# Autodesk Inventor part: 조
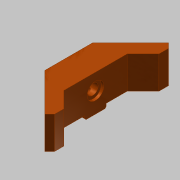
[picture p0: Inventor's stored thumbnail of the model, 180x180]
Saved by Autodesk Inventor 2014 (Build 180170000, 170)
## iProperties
Created: 2019-04
Part Number: 조
Material: 알루미늄 6061
Document SubType Name: Modeling
Designer: mduedu
Density: 1 g/cm^3
Appearance: Smooth - Light Orange
Author: mduedu
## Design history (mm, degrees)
sketch "스케치1"
  geometry: L1 (45.962, 0)-(0, -45.962); L2 (0, -45.962)-(-45.962, 0); L3 (-45.962, 0)-(0, 45.962); L4 (0, 45.962)-(45.962, 0); L5 (45.962, 0)-(-45.962, 0); L6 (0, -45.962)-(0, 45.962); 1 further point
  constraints: 12 end point, 2 midpoint, 2 parallel, 2 perpendicular, 1 horizontal
  dimensions: "d0" = 65 distance of L1.end L2.end
extrude "돌출1" new body sketch "스케치1" distance "d2" = 27; taper "d3" = 0 deg
chamfer "모따기1" distance "d4" = 25; stored, may be unused: second distance "d5" = 2, angle "d6" = 45 deg
sketch "스케치2"
  geometry: L1 (-17.678, 28.284)-(-45.962, 0) reference; L2 (-17.678, 28.284)-(17.678, 28.284) reference; L3 (45.962, 0)-(17.678, 28.284) reference; L4 (-45.962, 0)-(0, -45.962) reference; L5 (0, -45.962)-(45.962, 0) reference; L6 (-23.536, 8.284)-(23.536, 8.284); L7 (-23.536, 8.284)-(-38.891, -7.071); L8 (38.891, -7.071)-(23.536, 8.284); 1 further point
  constraints: 6 end point, 3 parallel, 2 point on line
  dimensions: "d7" = 20 distance between parallel lines of L6 L2; "d8" = 10 distance between parallel lines of L1 L7; "d9" = 10 distance between parallel lines of L3 L8
extrude "돌출2" cut sketch "스케치2" stored distance "d10" = 27; taper "d11" = 0 deg
sketch "스케치3"
  geometry: L1 (63.64, -27)-(63.64, 0) reference; L2 (56.569, -27)-(63.64, -27) reference; L3 (-28.284, -27)-(-28.284, 0) reference; L4 (-28.284, -27)-(-21.213, -27) reference; L5 (63.64, -27)-(25.678, -27); L6 (25.678, -27)-(25.678, -24); L7 (25.678, -24)-(63.64, -24); L8 (63.64, -24)-(63.64, -27); L9 (-28.284, -27)-(9.678, -27); L10 (9.678, -27)-(9.678, -24); L11 (9.678, -24)-(-28.284, -24); L12 (-28.284, -24)-(-28.284, -27); L13 (41.213, 0)-(-5.858, 0) reference; L14 (17.678, -27)-(17.678, 0)
  constraints: 18 end point, 4 parallel, 2 horizontal, 2 perpendicular, 1 midpoint, 1 symmetric about line
  dimensions: "d12" = 3 distance between parallel lines of L5 L7; "d14" = 16 distance between parallel lines of L10 L6
extrude "돌출3" cut sketch "스케치3" stored distance "d15" = 27; taper "d16" = 0 deg
sketch "스케치4"
  geometry: L1 (31.536, -27)-(15.536, -27) reference; L2 (31.536, -24)-(47.071, -24) reference; 3 further points
  constraints: 1 midpoint, 1 vertical alignment
  dimensions: "d17" = 12 distance from line of L2 point (23.536, -12)
hole "구멍1" sketch "스케치4" at (23.536, -12) diameter "d18" = 8; stored, may be unused: countersink angle "d22" = 90 deg, drill point angle "d24" = 118 deg; dims "d19" = 6, "d20" = 12.5, "d21" = 2, "d23" = 14
node "작업 평면1"
sketch "스케치5"
  geometry: L1 (0, -15)-(0, 0); L2 (-50, -4)-(50, -4); L3 (50, -4)-(50, -1.75); L4 (-50, -1.75)-(-50, -4); L5 (12, -1.75)-(12, -2.75); L6 (12, -2.75)-(-12, -2.75); L7 (-12, -2.75)-(-12, -1.75); L8 (50, -1.75)-(12, -1.75); L9 (-12, -1.75)-(-50, -1.75); C1 r 4 at (0, 0) reference; 2 further points
  constraints: 18 end point, 4 parallel, 2 midpoint, 2 vertical, 2 vertical alignment, 1 collinear, 1 horizontal, 1 perpendicular, 1 tangent
  dimensions: "d26" = 2.5 diameter of L6 L2; "d28" = 4.5 diameter of L8 L2; "d29" = 24 distance of L5.end L6.end; "d30" = 100 distance between parallel lines of L3 L4
revolve "회전1" sketch "스케치5" stored, may be unused: angle "d31" = 90 deg
chamfer "모따기2" distance "d32" = 5; stored, may be unused: second distance "d33" = 2, angle "d34" = 45 deg
chamfer "모따기3" distance "d35" = 1; stored, may be unused: second distance "d36" = 2, angle "d37" = 45 deg
node "솔리드1"
other parameters: "d25" = -5
